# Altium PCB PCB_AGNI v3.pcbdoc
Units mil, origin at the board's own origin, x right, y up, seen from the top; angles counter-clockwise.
Board outline 4895 x 4505 mil, 4 copper layers (Top Layer, GND, GND (Plane2), Bottom Layer); 85 components, 70 nets, 368 pads, 99 vias.
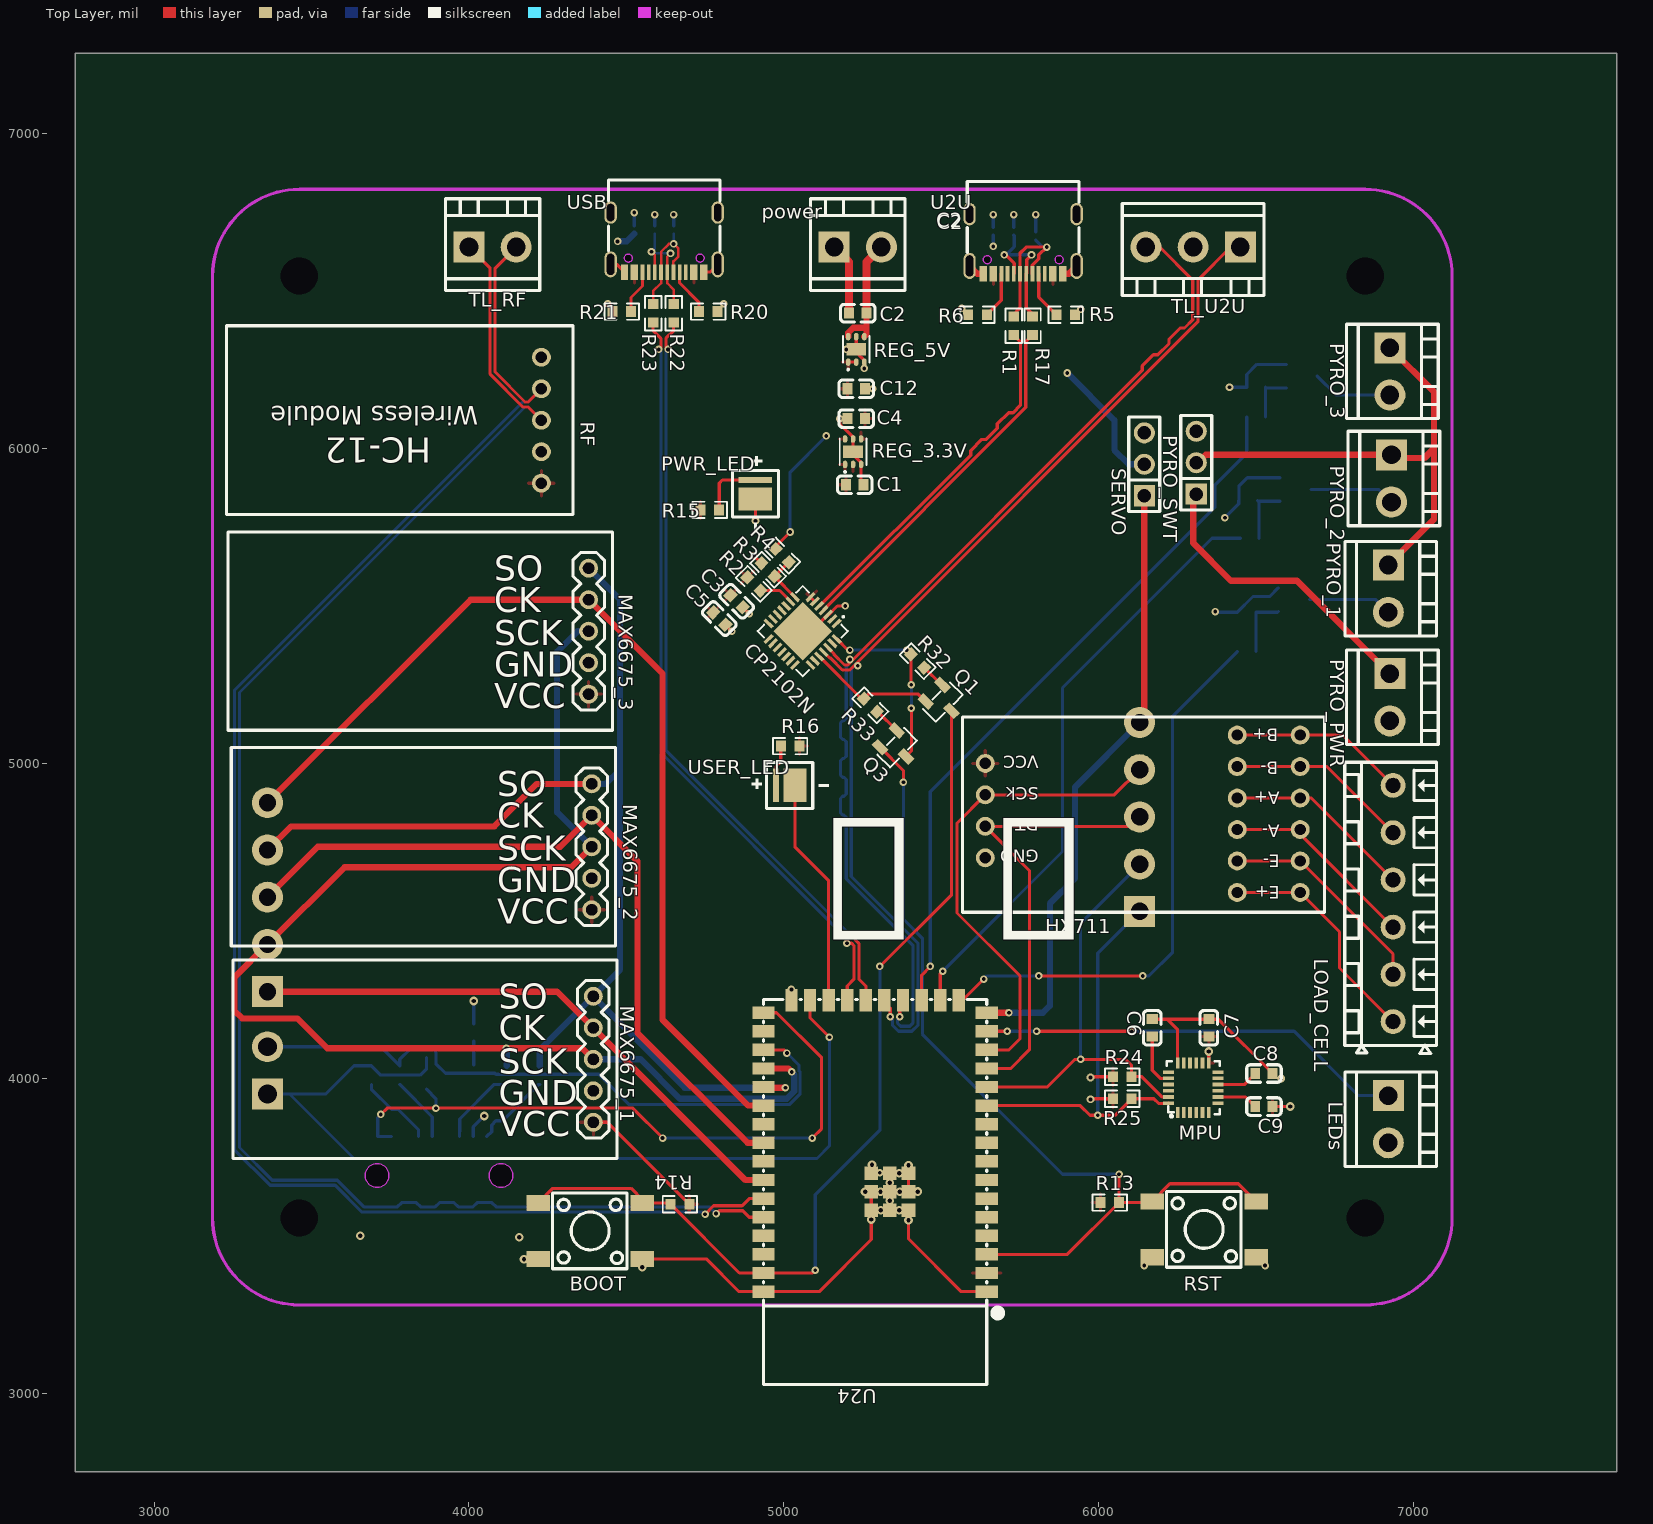
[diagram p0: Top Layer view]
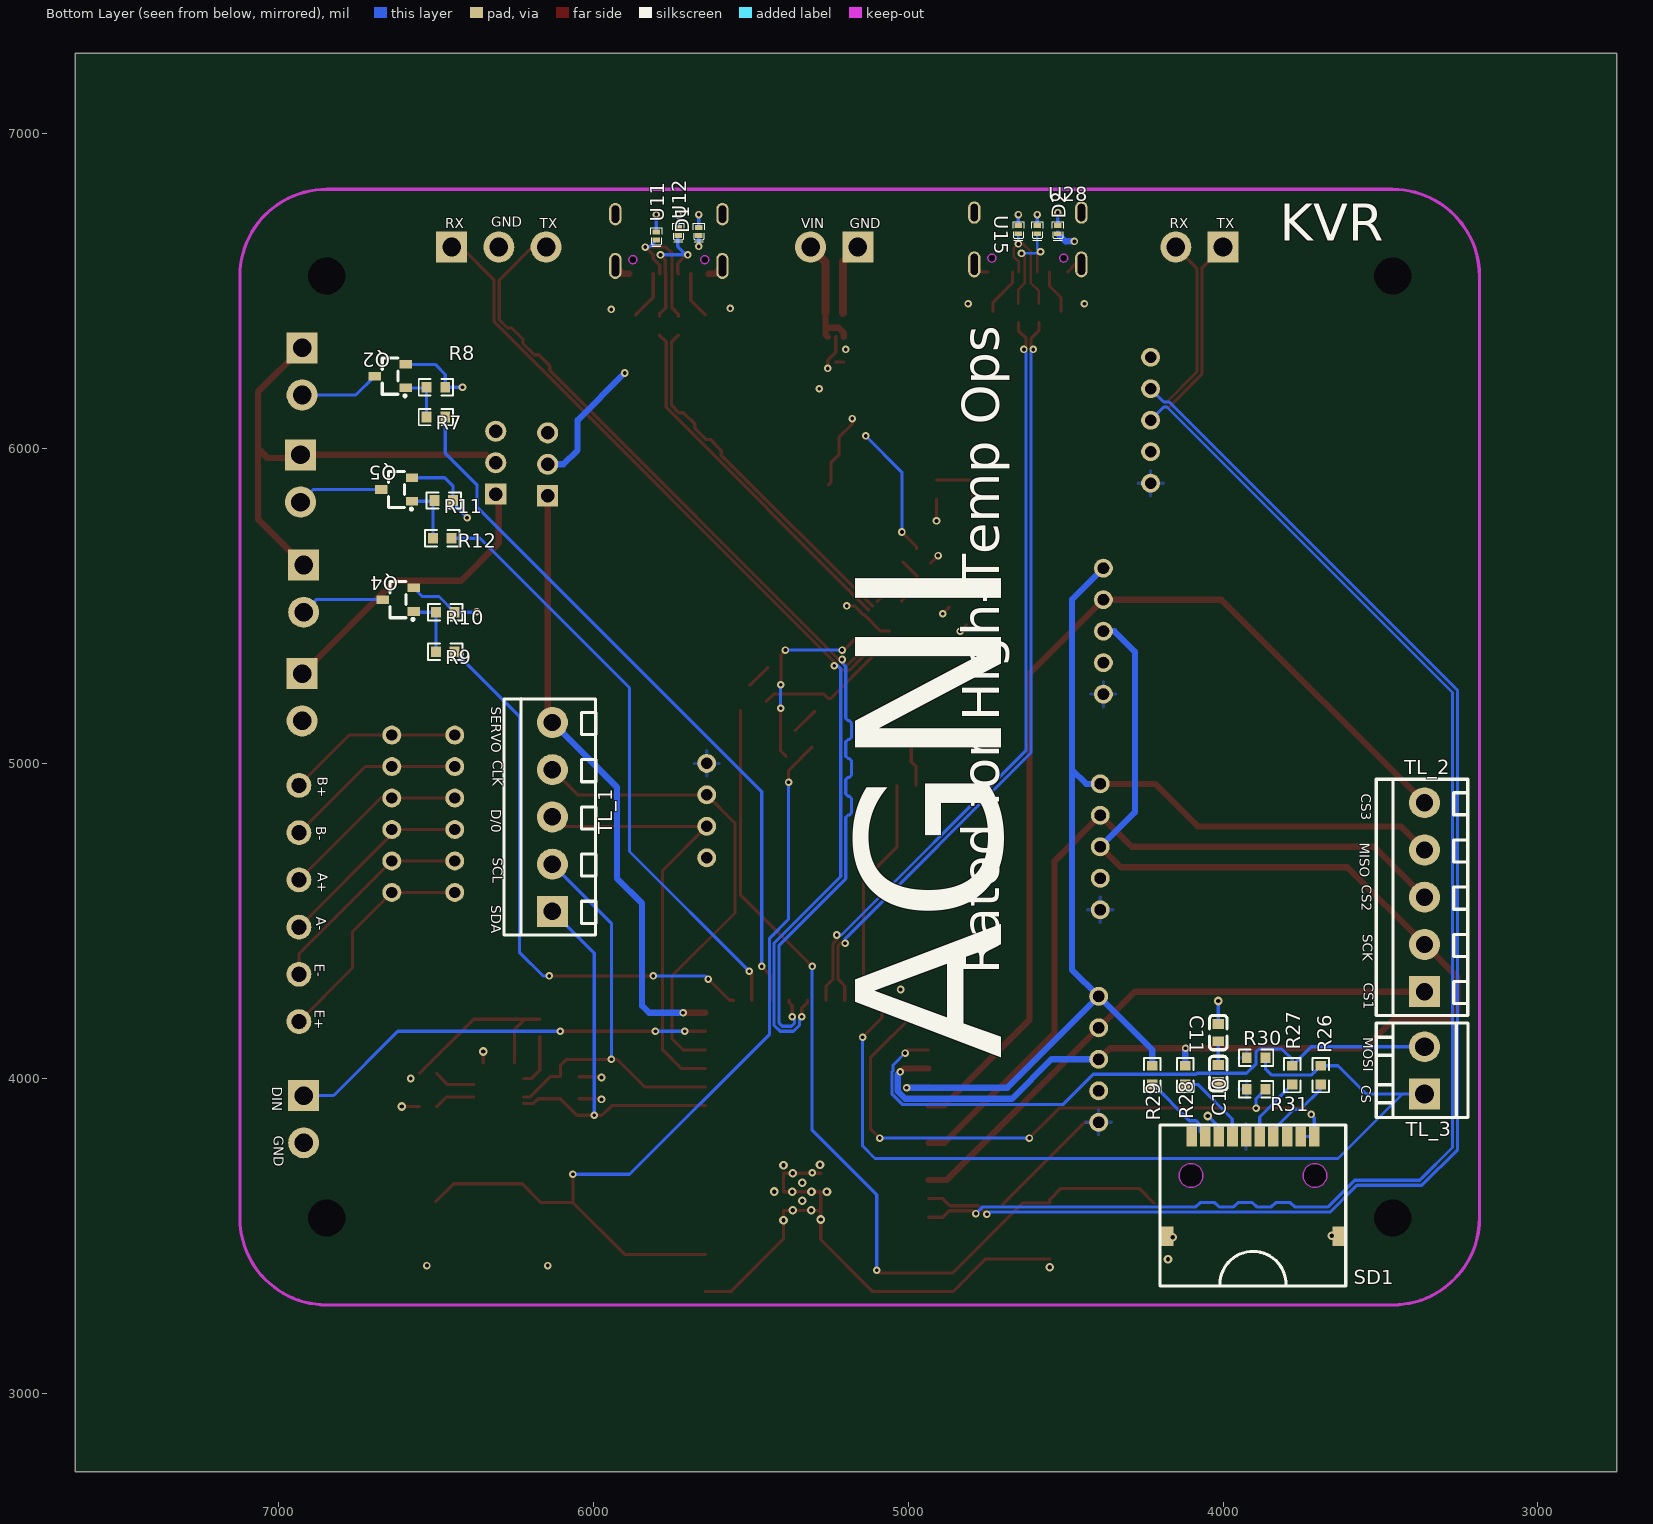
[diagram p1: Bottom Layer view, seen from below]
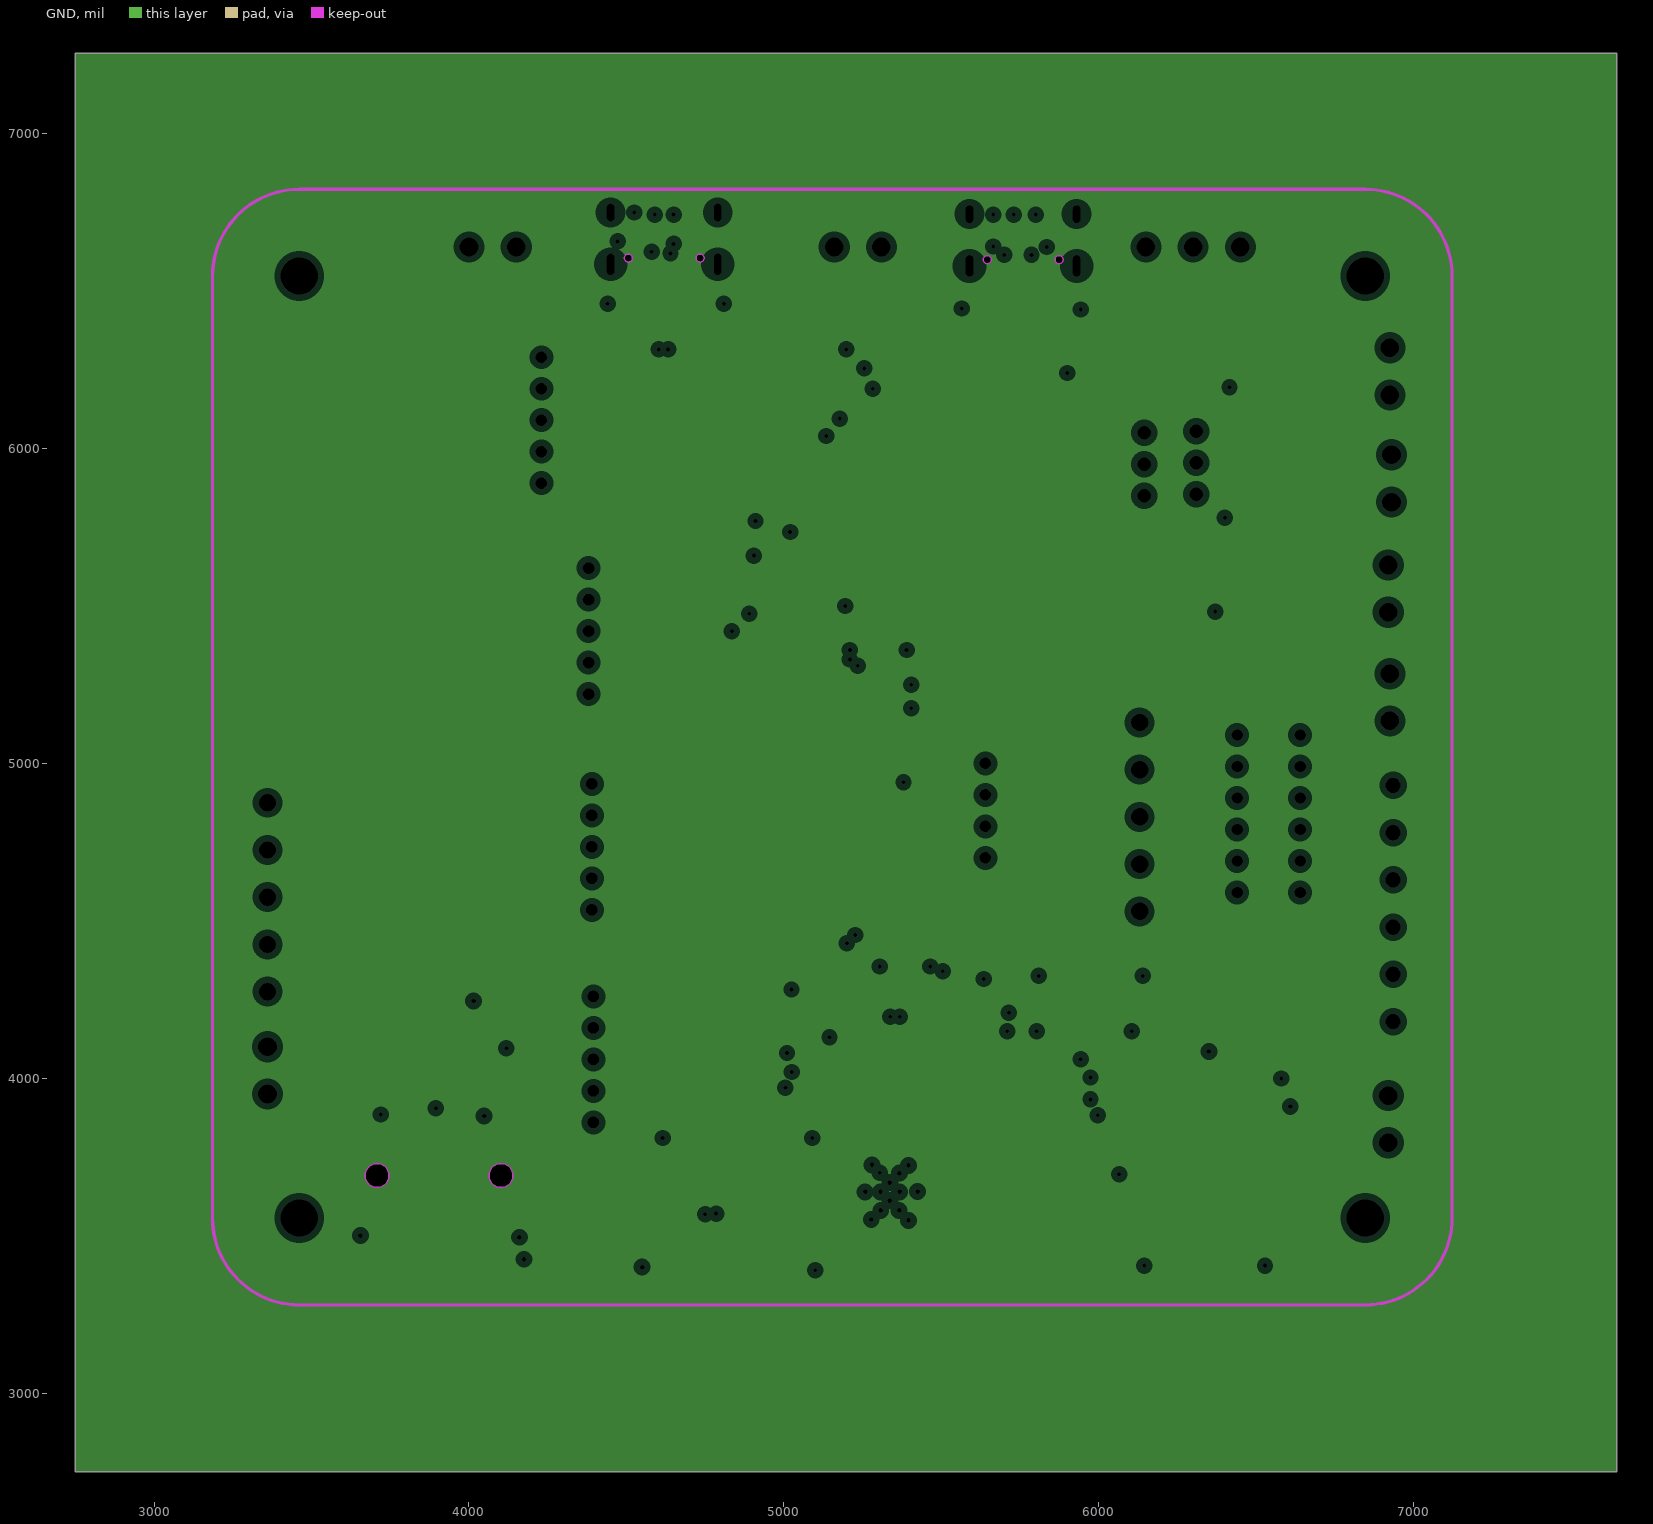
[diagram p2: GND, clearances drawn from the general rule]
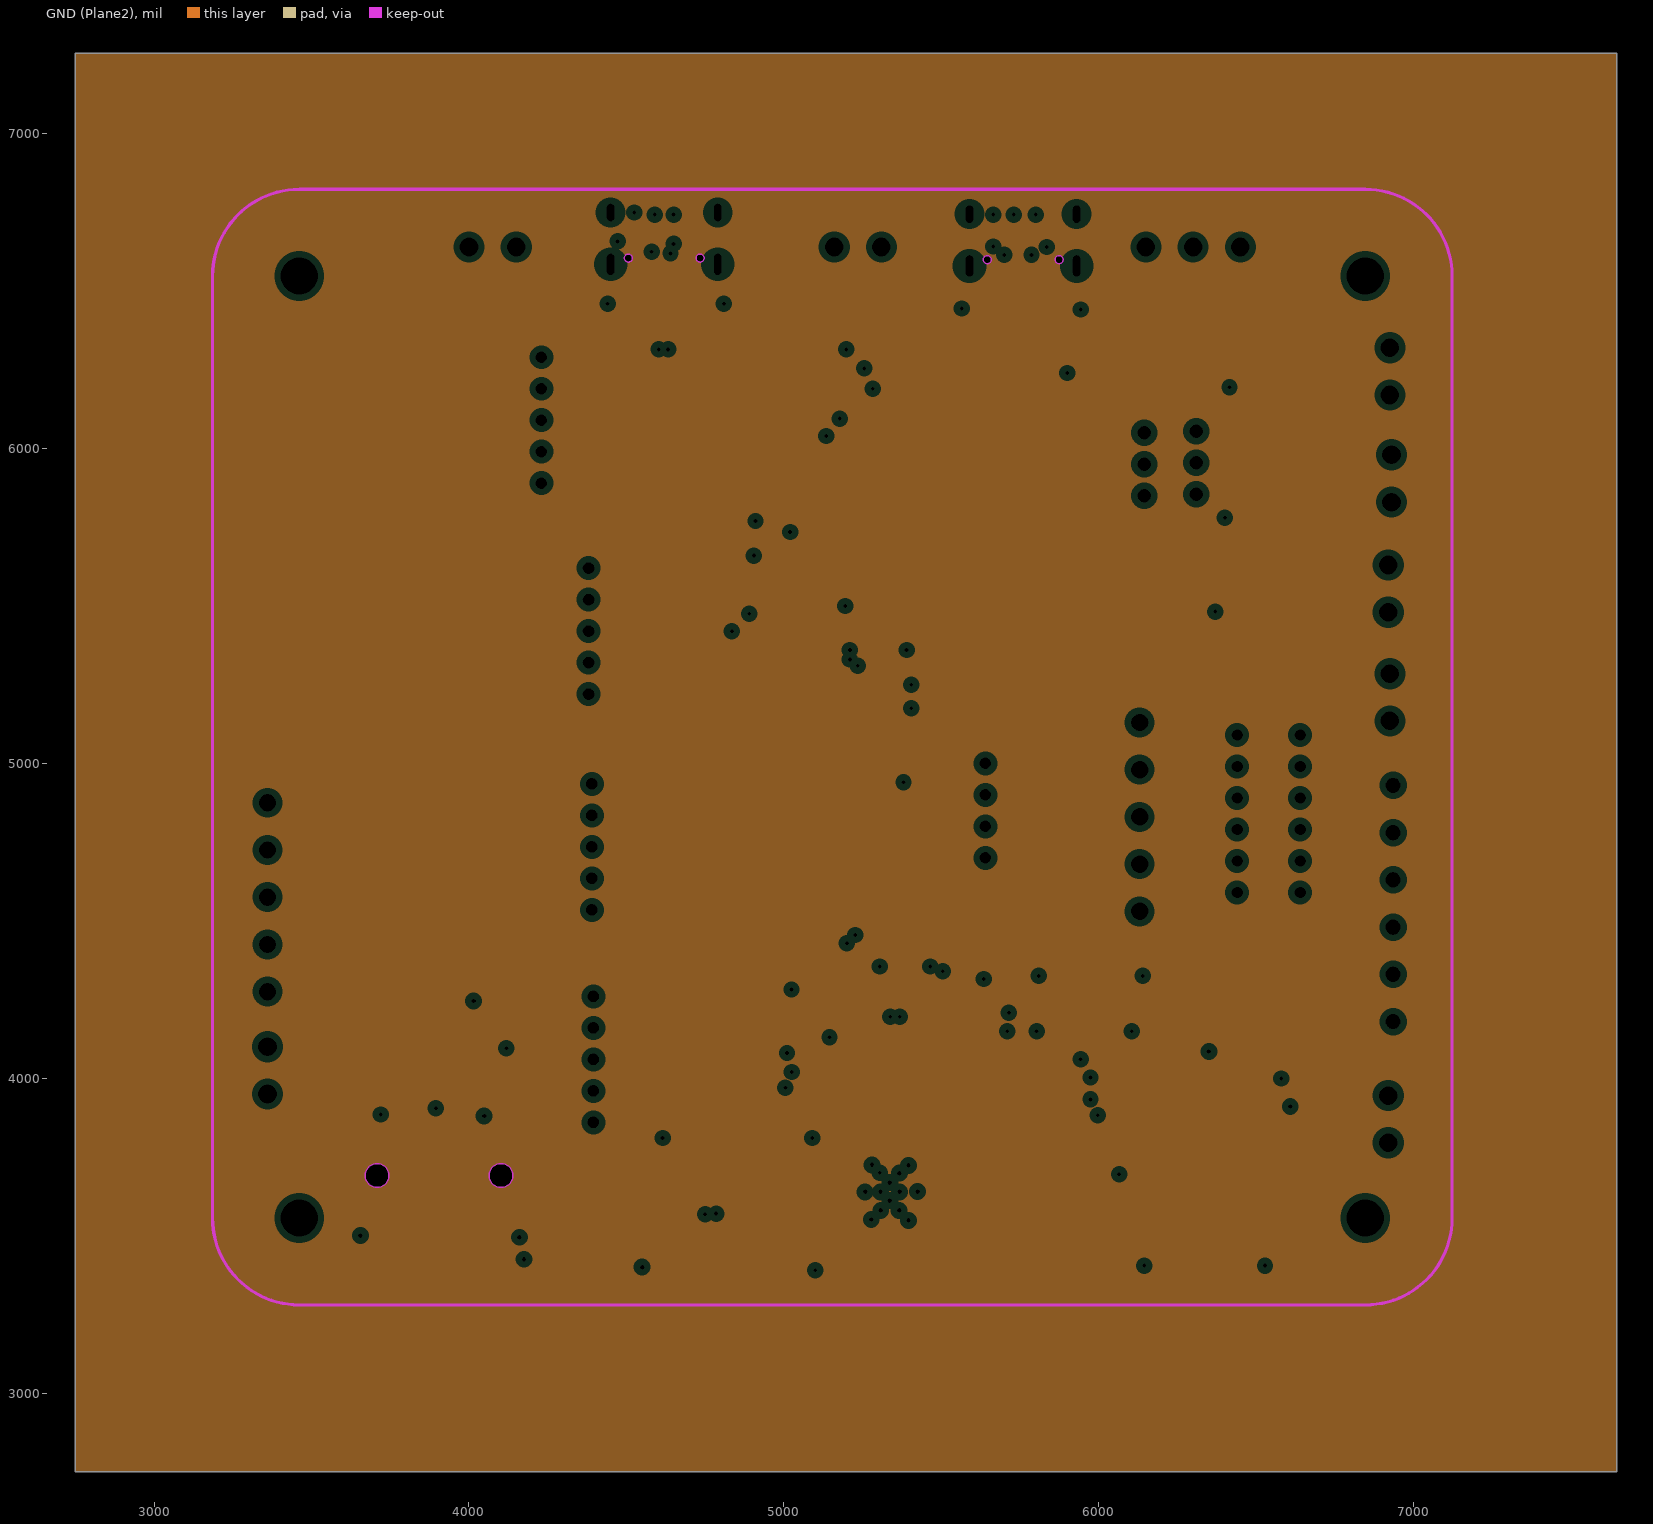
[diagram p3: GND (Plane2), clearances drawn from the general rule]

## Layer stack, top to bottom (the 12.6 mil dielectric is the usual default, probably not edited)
Top Layer: signal copper (thickness not stored)
Dielectric: dielectric 12.6, FR-4, Dk 4.8
GND: plane copper (thickness not stored)
Dielectric: dielectric 12.6, FR-4, Dk 4.8
GND (Plane2): plane copper (thickness not stored)
Dielectric: dielectric 12.6, FR-4, Dk 4.8
Bottom Layer: signal copper (thickness not stored)

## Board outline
7645,2750 2750,2750 2750,7255 7645,7255

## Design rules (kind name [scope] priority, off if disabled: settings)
BoardOutlineClearance copperThickness1oz [All] p0: genericclearance=10 ignorepadtopadclearanceinfootprint=FALSE except(0: Arc-SplitContinuation Track-SplitContinuation SMDPad-SplitContinuation THPad-SplitContinuation Via-SplitContinuation Fill-SplitContinuation Poly-SplitContinuation Region-SplitContinuation Text-SplitContinuation; 6: SMDPad-CutoutEdge THPad-CutoutEdge Via-CutoutEdge Fill-CutoutEdge Region-CutoutEdge; 11.8: Track-OutlineEdge SMDPad-OutlineEdge THPad-OutlineEdge Via-OutlineEdge Fill-OutlineEdge Region-OutlineEdge Poly-OutlineEdge Text-OutlineEdge Track-CutoutEdge)
BoardOutlineClearance copperThickness2oz [All] p0: genericclearance=10 ignorepadtopadclearanceinfootprint=FALSE except(0: Arc-SplitContinuation Track-SplitContinuation SMDPad-SplitContinuation THPad-SplitContinuation Via-SplitContinuation Fill-SplitContinuation Poly-SplitContinuation Region-SplitContinuation Text-SplitContinuation; 6: SMDPad-CutoutEdge THPad-CutoutEdge Via-CutoutEdge Fill-CutoutEdge Region-CutoutEdge; 11.8: Track-OutlineEdge SMDPad-OutlineEdge THPad-OutlineEdge Via-OutlineEdge Fill-OutlineEdge Region-OutlineEdge Poly-OutlineEdge Text-OutlineEdge Track-CutoutEdge)
BoardOutlineClearance copperThicknessInner0.5oz [All] p0: genericclearance=10 ignorepadtopadclearanceinfootprint=FALSE except(0: Arc-SplitContinuation Track-SplitContinuation SMDPad-SplitContinuation THPad-SplitContinuation Via-SplitContinuation Fill-SplitContinuation Poly-SplitContinuation Region-SplitContinuation Text-SplitContinuation; 6: SMDPad-CutoutEdge THPad-CutoutEdge Via-CutoutEdge Fill-CutoutEdge Region-CutoutEdge; 11.8: Track-OutlineEdge SMDPad-OutlineEdge THPad-OutlineEdge Via-OutlineEdge Fill-OutlineEdge Region-OutlineEdge Poly-OutlineEdge Text-OutlineEdge Track-CutoutEdge)
Clearance copperThickness1oz [(InNet('USB_D+') OR InNet('USB_D-') OR InNet('D+') OR InNet('D-') OR InNet('VIN') OR InNet('GND') OR InNet('+5V') OR InNet('MOSI') OR InNet('CS') OR InNet('PYRO-3') OR InNet('PYRO-1') OR InNet('PYRO-2') OR InNet('CD') OR InNet('3.3') OR InNet('SCK') OR InNet('MISO') OR InNet('CS3') OR InNet('CS2') OR InNet('CS1') OR InNet('SERVO_HIGH') OR InNet('CLK') OR InNet('D/O') OR InNet('SCL') OR InNet('SDA') OR InNet('PYRO_5V') OR InNet('PYRO_ARM') OR InNet('UART_D+') OR InNet('UART_D-') OR InNet('RTS') OR InNet('U2U_RX') OR InNet('U2U_TX') OR InNet('DTR') OR InNet('IO0') OR InNet('EN') OR InNet('RF_TX') OR InNet('RF_RX') OR InNet('LED_USER') OR InNet('DIN_LED') OR InNet('$1N118') OR InNet('$1N2149') OR InNet('$1N121') OR InNet('$1N129') OR InNet('1D-') OR InNet('$1N23') OR InNet('$1N18') OR InNet('$1N68') OR InNet('$1N69') OR InNet('$1N96') OR InNet('$1N98') OR InNet('$1N99') OR InNet('1D+') OR InNet('$1N9') OR InNet('$1N8') OR InNet('$1N134') OR InNet('$1N147') OR InNet('$1N149') OR InNet('$1N41') OR InNet('$1N48') OR InNet('$1N36') OR InNet('$1N102') OR InNet('$1N103') OR InNet('$1N106') OR InNet('$1N105') OR InNet('$1N104') OR InNet('$1N190') OR InNet('$1N40') OR InNet('$1N49') OR InNet('$1N123') OR InNet('$1N125') OR InNet('$1N131'))] p1: gap=7 ignorepadtopadclearanceinfootprint=FALSE except(4: Track-Track; 6: Track-SMDPad SMDPad-SMDPad Track-THPad SMDPad-THPad THPad-THPad Track-Via SMDPad-Via THPad-Via Via-Via Track-Fill SMDPad-Fill THPad-Fill Via-Fill Fill-Fill SMDPad-Region THPad-Region Via-Region Fill-Region Region-Region Track-Poly SMDPad-Poly THPad-Poly Via-Poly Fill-Poly Poly-Poly Track-Text SMDPad-Text THPad-Text Via-Text Fill-Text Region-Text Poly-Text Text-Text; 6.9: Track-Hole SMDPad-Hole THPad-Hole Via-Hole Fill-Hole Region-Hole Poly-Hole Text-Hole Sheet-Hole; 11.8: Track-Region Region-Poly Track-Sheet SMDPad-Sheet THPad-Sheet Via-Sheet Fill-Sheet Region-Sheet Poly-Sheet Text-Sheet)
Clearance copperThickness2oz [All] p1: gap=7 ignorepadtopadclearanceinfootprint=FALSE except(6: Track-SMDPad SMDPad-SMDPad Track-THPad SMDPad-THPad THPad-THPad Track-Via SMDPad-Via THPad-Via Via-Via Track-Fill SMDPad-Fill THPad-Fill Via-Fill Fill-Fill SMDPad-Region THPad-Region Via-Region Fill-Region Region-Region Track-Poly SMDPad-Poly THPad-Poly Via-Poly Fill-Poly Poly-Poly Track-Text SMDPad-Text THPad-Text Via-Text Fill-Text Region-Text Poly-Text Text-Text; 6.9: Track-Hole SMDPad-Hole THPad-Hole Via-Hole Fill-Hole Region-Hole Poly-Hole Text-Hole Sheet-Hole; 8: Track-Track; 11.8: Track-Region Region-Poly Track-Sheet SMDPad-Sheet THPad-Sheet Via-Sheet Fill-Sheet Region-Sheet Poly-Sheet Text-Sheet)
Clearance copperThicknessInner0.5oz [All] p1: gap=7 ignorepadtopadclearanceinfootprint=FALSE except(3.5: Track-Track; 6: Track-SMDPad SMDPad-SMDPad Track-THPad SMDPad-THPad THPad-THPad Track-Via SMDPad-Via THPad-Via Via-Via Track-Fill SMDPad-Fill THPad-Fill Via-Fill Fill-Fill SMDPad-Region THPad-Region Via-Region Fill-Region Region-Region Track-Poly SMDPad-Poly THPad-Poly Via-Poly Fill-Poly Poly-Poly Track-Text SMDPad-Text THPad-Text Via-Text Fill-Text Region-Text Poly-Text Text-Text; 6.9: Track-Hole SMDPad-Hole THPad-Hole Via-Hole Fill-Hole Region-Hole Poly-Hole Text-Hole Sheet-Hole; 11.8: Track-Region Region-Poly Track-Sheet SMDPad-Sheet THPad-Sheet Via-Sheet Fill-Sheet Region-Sheet Poly-Sheet Text-Sheet)
DiffPairsRouting differentialPair [All] p1: maxuncoupledlength=10 minlimit=5.9843 maxlimit=5.9843 mostfreqgap=5.9843 toplayer_minwidth=5 toplayer_prefwidth=10 toplayer_maxwidth=100 bottomlayer_minwidth=5 bottomlayer_prefwidth=10 bottomlayer_maxwidth=100
PasteMaskExpansion pasteMaskExpansion [All] p1: expansion=0
PlaneConnect innerPlane [All] p1: planeconnectstyle=Relief reliefexpansion=20 reliefentries=4 reliefconductorwidth=10 reliefairgap=10
PolygonConnect copperRegion [All] p1: connectstyle=Relief reliefentries=4 reliefconductorwidth=10 polygonreliefangle="90 Angle" airgapwidth=10
RoutingVias viaSize [All] p1: viastyle="Through Hole" holewidth=12.0078 minholewidth=7.874 maxholewidth=248.0314 width=24.0158 minwidth=11.811 maxwidth=393.7008
SolderMaskExpansion solderMaskExpansion [All] p1: useseparateexpansions=TRUE expansion=2.0079 expansionbottom=2.0079
Width copperThickness1oz [All] p1: maxlimit=100 minlimit=4 preferedwidth=10
Width copperThickness0.5oz [All] p1: maxlimit=100 minlimit=4 preferedwidth=10
Width copperThickness2oz [All] p1: maxlimit=100 minlimit=8 preferedwidth=10

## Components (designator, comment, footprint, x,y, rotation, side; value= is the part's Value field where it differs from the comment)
BOOT "PTS645SH50SMTR92LFS" KEY-SMD_4P-L6.0-W6.0-P4.50-LS9.0 4385,3515 r0 top locked
C1 "2.2uF" C0603 5225,5885 r180 top locked
C2 "1uF" C0603 5235,6430 r0 top locked
C3 "10uF" C0603 4850,5515 r135 top locked
C4 "1uF" C0603 5230,6095 r0 top locked
C5 "10uF" C0603 4795,5460 r135 top locked
C6 "2.2nF" C0603 6170,4160 r270 top locked
C7 "0.1uF" C0603 6350,4160 r90 top locked
C8 "0.1uF" C0603 6525,4015 r180 top locked
C9 "10nF" C0603 6525,3910 r0 top locked
C10 "0.1uF" C0603 4015,4015 r270 bottom locked
C11 "10uF" C0603 4015,4145 r270 bottom locked
C12 "2.2uF" C0603 5230,6190 r180 top locked
CP2102N "CP2102N-A02-GQFN28R" QFN-28_L5.0-W5.0-P0.50-TL-EP3.3 5060,5420 r225 top locked
D1 "ESD351DPYR" X1SON-2_L1.0-W0.6-P0.65-RD-1 5665,6690 r90 bottom locked
D2 "ESD351DPYR" X1SON-2_L1.0-W0.6-P0.65-RD-1 4525,6695 r90 bottom locked
HX711 "HX711 LOAD CELL AMPLIFIER COMBINE" "HX711 LOAD CELL AMPLIFIER HX711 BREAKOUT" 6140,4840 r180 top locked
LEDs "DB125-3.81-2P-RD" CONN-TH_DB125-3.81-2P-RD 6920,3870 r270 top locked
LOAD_CELL "DB125-3.81-6P-GN-S" CONN-TH_DB125-3.81-6P-GN-S 6935,4555 r90 top locked
MAX6675_1 "MAX6675" MAX6675 4395,4060 r0 top locked
MAX6675_2 "MAX6675" MAX6675 4390,4735 r0 top locked
MAX6675_3 "MAX6675" MAX6675 4380,5420 r0 top locked
MPU "MPU6050_C9900042518" QFN-24_L4.0-W4.0-P0.50-BL 6300.01,3970.04 r0 top locked
power "DB125-3.81-2P-RD" CONN-TH_DB125-3.81-2P-RD 5235,6640 r0 top locked
PWR_LED "720-LCGH9RNMXNX1" LED-SMD_SD65-120-LED 4910,5870 r90 top locked
PYRO_1 "DB125-3.81-2P-RD" CONN-TH_DB125-3.81-2P-RD 6920,5555 r270 top locked
PYRO_2 "DB125-3.81-2P-RD" CONN-TH_DB125-3.81-2P-RD 6930,5905 r270 top locked
PYRO_3 "DB125-3.81-2P-RD" CONN-TH_DB125-3.81-2P-RD 6925,6245 r270 top locked
PYRO_PWR "DB125-3.81-2P-RD" CONN-TH_DB125-3.81-2P-RD 6925,5210 r270 top locked
PYRO_SWT "HDR-M_2.54_1x3P" HDR-TH_3P-P2.54-V-M 6310,5955 r90 top locked
Q1 "SS8050G-Y1" SOT-23-3_L2.9-W1.3-P1.90-LS2.4-BR 5505,5195 r135 top locked
Q2 "A03400" SOT-23-3_L2.9-W1.3-P1.90-LS2.6-BR 6645,6230 r180 bottom locked
Q3 "SS8050G-Y1" SOT-23-3_L2.9-W1.3-P1.90-LS2.4-BR 5360,5050 r135 top locked
Q4 "A03400" SOT-23-3_L2.9-W1.3-P1.90-LS2.6-BR 6620,5520 r180 bottom locked
Q5 "A03400" SOT-23-3_L2.9-W1.3-P1.90-LS2.6-BR 6625,5870 r180 bottom locked
R1 "22" R0603 5730,6390 r90 top locked
R2 "1k" R0603 4905,5570 r135 top locked
R3 "47K" R0603 4950,5615 r135 top locked
R4 "24K" R0603 4995,5660 r315 top locked
R5 "5.1K" R0603 5895,6425 r180 top locked
R6 "5.1k" R0603 5615,6425 r0 top locked
R7 "220" R0603 6500,6100 r0 bottom locked
R8 "10K" R0603 6500,6195 r0 bottom locked
R9 "220" R0603 6470,5355 r0 bottom locked
R10 "10K" R0603 6470,5480 r0 bottom locked
R11 "10K" R0603 6475,5835 r0 bottom locked
R12 "220" R0603 6480,5715 r0 bottom locked
R13 "10K" R0603 6035,3605 r180 top locked
R14 "10K" R0603 4670,3600 r0 top locked
R15 "220" R0603 4765,5805 r180 top locked
R16 "220" R0603 5020,5055 r0 top locked
R17 "22" R0603 5790,6390 r90 top locked
R20 "5.1K" R0603 4760,6435 r180 top locked
R21 "5.1k" R0603 4485,6435 r0 top locked
R22 "22" R0603 4650,6430 r90 top locked
R23 "22" R0603 4585,6430 r90 top locked
R24 "4.7K" R0603 6075,4005 r0 top locked
R25 "4.7K" R0603 6075,3935 r180 top locked
R26 "33" R0603 3690,4010 r90 bottom locked
R27 "33" R0603 3780,4010 r90 bottom locked
R28 "33" R0603 4120,4010 r90 bottom locked
R29 "33" R0603 4225,4010 r90 bottom locked
R30 "4.7" R0603 3895,4065 r180 bottom locked
R31 "10k" R0603 3895,3965 r180 bottom locked
R32 "10K" R0603 5425,5325 r135 top locked
R33 "10K" R0603 5275,5185 r135 top locked
REG_3.3V "TLV76733DRVT" WSON-6_L2.0-W2.0-P0.65-TL-EP 5220,5990 r90 top locked
REG_5V "TLV76750DRVT" WSON-6_L2.0-W2.0-P0.65-TL-EP 5230,6315 r90 top locked
RF "HC-12 SI44663" "HC-12 SI4463 WIRELESS MODULE" 4330,5790 r180 top locked
RST "PTS645SH50SMTR92LFS" KEY-SMD_4P-L6.0-W6.0-P4.50-LS9.0 6335,3520 r0 top locked
SD1 "SUNROM 6174" "SUNROM 6174" 3905,3815 r0 bottom locked
SERVO "HDR-M_2.54_1x3P" HDR-TH_3P-P2.54-V-M 6145,5950 r90 top locked
TL_1 "DB125-3.81-5P-GN-S" CONN-TH_DB125-3.81-5P-GN-S 6130,4830 r90 bottom locked
TL_2 "DB125-3.81-5P-GN-S" CONN-TH_DB125-3.81-5P-GN-S 3360,4575 r90 bottom locked
TL_3 "DB125-3.81-2P-RD" CONN-TH_DB125-3.81-2P-RD 3360,4025 r90 bottom locked
TL_RF "DB125-3.81-2P-RD" CONN-TH_DB125-3.81-2P-RD 4075,6640 r0 top locked
TL_U2U "DB125-3.81-3P-BK" CONN-TH_DB125-3.81-3P-BK 6300,6640 r180 top locked
U2U "GT-USB-7010ASV" USB-C-SMD_G-SWITCH_GT-USB-7010ASV 5760,6650 r180 top locked
U11 "ESD321DPYR" X1SON-2_L1.0-W0.6-P0.65-RD 5800,6675 r90 bottom locked
U12 "ESD321DPYR" X1SON-2_L1.0-W0.6-P0.65-RD 5730,6690 r90 bottom locked
U15 "ESD321DPYR" X1SON-2_L1.0-W0.6-P0.65-RD 4650,6695 r90 bottom locked
U24 "ESP32-S2-WROOM(4M)" WIFI-SMD_ESP32-S2-WROVER-I 5290,3785 r180 top locked
U28 "ESD321DPYR" X1SON-2_L1.0-W0.6-P0.65-RD 4590,6695 r90 bottom locked
USB "GT-USB-7010ASV" USB-C-SMD_G-SWITCH_GT-USB-7010ASV 4620,6655 r180 top locked
USER_LED "720-LCGH9RNMXNX1" LED-SMD_SD65-120-LED 5005,4930 r180 top locked

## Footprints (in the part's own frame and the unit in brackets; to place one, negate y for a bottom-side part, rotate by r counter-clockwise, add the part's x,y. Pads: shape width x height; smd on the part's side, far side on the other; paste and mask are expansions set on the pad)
C0603 [mm]
  rect 0.8x0.9 smd: 1(-0.7,0) 2(0.7,0)
  silkscreen extent -1.39,-0.71 1.39,0.71
CONN-TH_DB125-3.81-2P-RD [mm]
  rect 2.5x2.5 hole 1.5: 1(-1.905,0)
  round 2.5 hole 1.5: 2(1.905,0)
  silkscreen extent -3.81,-3.5 3.81,3.9
CONN-TH_DB125-3.81-3P-BK [mm]
  rect 2.5x2.5 hole 1.5: 1(-3.81,0)
  round 2.5 hole 1.5: 2(0,0) 3(3.81,0)
  silkscreen extent -5.72,-3.5 5.72,3.9
CONN-TH_DB125-3.81-5P-GN-S [mm]
  rect 2.5x2.5 hole 1.4: 1(-7.62,0)
  round 2.5 hole 1.4: 2(-3.81,0) 3(0,0) 4(3.81,0) 5(7.62,0)
  silkscreen extent -9.53,-3.5 9.53,3.9
CONN-TH_DB125-3.81-6P-GN-S [mm]
  round 2 hole 1.2 slot 1.205 at 0 deg: 1(-9.525,0) 2(-5.715,0) 3(-1.905,0) 4(1.905,0) 5(5.715,0) 6(9.525,0)
  silkscreen extent -12.1,-3.5 11.4,3.9
"HC-12 SI4463 WIRELESS MODULE" [mil]
  round 60 hole 36: 1(100,-100) 2(100,-200) 3(100,-300) 4(100,-400) 5(100,-500)
  silkscreen extent 0,-600 1100,0
HDR-TH_3P-P2.54-V-M [mm]
  rect 1.7x1.7 hole 1.1: 1(-2.54,0)
  round 1.7 hole 1.1: 2(0,0) 3(2.54,0)
  silkscreen extent -3.81,-1.25 3.81,1.25
"HX711 LOAD CELL AMPLIFIER HX711 BREAKOUT" [mil]
  round 60 hole 36 copper offset -0.01,0.01: 1(-499.99,249.99) 1(-299.99,249.99) 2(-499.99,149.99) 2(-299.99,149.99) 3(-499.99,49.99) 3(-299.99,49.99) 4(-499.99,-50.01) 4(-299.99,-50.01) 5(-499.99,-150.01) 5(-299.99,-150.01) 6(-499.99,-250.01) 6(-299.99,-250.01) 8(500.01,39.99) 9(500.01,-60.01) 10(500.01,-160.01)
  round 60 hole 36 copper offset -0.01,0: 7(500.01,140)
  silkscreen extent -577,-308 573,313
KEY-SMD_4P-L6.0-W6.0-P4.50-LS9.0 [mm]
  rect 1.9x1.3 smd: 1(-4.2,2.25) 2(4.2,2.25) 3(-4.2,-2.25) 4(4.2,-2.25)
  silkscreen extent -3.05,-3.05 2.98,3.05
LED-SMD_SD65-120-LED [mm]
  rect 1.85x2.7 smd: 1(-0.763,0)
  rect 0.5x2.7 smd: 2(0.763,0)
  silkscreen extent -3.5,-1.85 2.7,1.85
MAX6675 [mil]
  round 60 hole 36 slot 36.2 at 0 deg: 1(0,200) 2(0,100) 3(0,0) 4(0,-100) 5(0,-200)
  silkscreen extent -1145,-315 75,315
QFN-24_L4.0-W4.0-P0.50-BL [mm]
  rect 0.3x0.9 smd: 1(-1.25,-2) 2(-0.75,-2) 3(-0.25,-2) 4(0.25,-2) 5(0.75,-2) 6(1.25,-2) 13(1.25,2) 14(0.75,2) 15(0.25,2) 16(-0.25,2) 17(-0.75,2) 18(-1.25,2)
  rect 0.9x0.3 smd: 7(2,-1.25) 8(2,-0.75) 9(2,-0.25) 10(2,0.25) 11(2,0.75) 12(2,1.25) 19(-2,1.25) 20(-2,0.75) 21(-2,0.25) 22(-2,-0.25) 23(-2,-0.75) 24(-2,-1.25)
  silkscreen extent -2.14,-2.4 2.16,2.15
QFN-28_L5.0-W5.0-P0.50-TL-EP3.3 [mm]
  rect 0.905x0.28 smd: 1(-2.377,1.5) 2(-2.377,1) 3(-2.377,0.5) 4(-2.378,0) 5(-2.377,-0.5) 6(-2.377,-1) 7(-2.377,-1.5) 15(2.377,-1.5) 16(2.377,-1) 17(2.377,-0.5) 18(2.378,0) 19(2.377,0.5) 20(2.377,1) 21(2.377,1.5)
  rect 0.28x0.905 smd: 8(-1.5,-2.377) 9(-1,-2.377) 10(-0.5,-2.377) 11(0,-2.378) 12(0.5,-2.377) 13(1,-2.377) 14(1.5,-2.377) 22(1.5,2.377) 23(1,2.377) 24(0.5,2.377) 25(0,2.378) 26(-0.5,2.377) 27(-1,2.377) 28(-1.5,2.377)
  rect 3.35x3.35 smd: 29(0,0)
  silkscreen extent -3.2,-2.58 2.58,2.58
R0603 [mil]
  rect 31.75x34.02 smd: 1(-29.66,0) 2(29.66,0)
  silkscreen extent -55,-26 55,26
SOT-23-3_L2.9-W1.3-P1.90-LS2.4-BR [mm]
  rect 1.25x0.7 smd: 1(1,-0.95) 2(1,0.95) 3(-1,0)
  silkscreen extent -0.73,-1.53 0.73,1.53
SOT-23-3_L2.9-W1.3-P1.90-LS2.6-BR [mm]
  rect 1x0.7 smd: 1(1.25,-0.95) 2(1.25,0.95) 3(-1.25,0)
  silkscreen extent -0.65,-1.69 1.29,1.46
"SUNROM 6174" [mm]
  rect 0.85x1.6 smd: 1(-2.75,0) 2(-1.65,0) 3(-0.55,0) 4(0.55,0) 5(1.65,0) 6(2.75,0) 7(3.85,0) 8(4.95,0) 9(-4.95,0) 10(-3.85,0)
  rect 1.15x1.6 smd: 11(-6.99,8.05) 12(6.99,8.05)
  Board Outline Layer lines w0.005: -5.003,2.198 cw(c-5.001,3.15) -5,2.198 -5.003,2.198 ; 4.997,2.198 cw(c4.999,3.15) 5,2.198 4.997,2.198
  Board Outline Layer region: -5,2.198 -4.524,2.326 -4.176,2.675 -4.049,3.151 -4.177,3.626 -4.525,3.975 -5.001,4.102 -5.477,3.975 -5.825,3.626 -5.953,3.151 -5.826,2.675 -5.478,2.326 -5.003,2.198 -5.003,2.198
  Board Outline Layer region: 5,2.198 5.476,2.326 5.824,2.675 5.951,3.151 5.823,3.626 5.475,3.975 4.999,4.102 4.523,3.975 4.174,3.626 4.047,3.151 4.174,2.675 4.522,2.326 4.997,2.198 4.997,2.198
  Multi-Layer board cut-out: -5,2.198 -4.524,2.326 -4.176,2.675 -4.049,3.151 -4.177,3.626 -4.525,3.975 -5.001,4.102 -5.477,3.975 -5.825,3.626 -5.953,3.151 -5.826,2.675 -5.478,2.326 -5.003,2.198 -5.003,2.198
  Multi-Layer board cut-out: 5,2.198 5.476,2.326 5.824,2.675 5.951,3.151 5.823,3.626 5.475,3.975 4.999,4.102 4.523,3.975 4.174,3.626 4.047,3.151 4.174,2.675 4.522,2.326 4.997,2.198 4.997,2.198
  silkscreen extent -7.49,-0.93 7.51,12.06
USB-C-SMD_G-SWITCH_GT-USB-7010ASV [mm]
  oval 1x2.1 hole 0.6 slot 1.7 at 90 deg: 1(-4.32,1.78) 2(4.32,1.78)
  oval 1x1.8 hole 0.6 slot 1.4 at 90 deg: 3(4.32,-2.4) 4(-4.32,-2.4)
  rect 0.6x1.24 smd: A1B12(-3.2,2.4) A4B9(-2.4,2.4) B1A12(3.2,2.4) B4A9(2.4,2.4)
  rect 0.3x1.24 smd: A5(-1.25,2.4) A6(-0.25,2.4) A7(0.25,2.4) A8(1.25,2.4) B5(1.75,2.4) B6(0.75,2.4) B7(-0.75,2.4) B8(-1.75,2.4)
  Board Outline Layer circle w0.005: c2.89,1.27 r0.325
  Board Outline Layer circle w0.005: c-2.9,1.27 r0.325
  Board Outline Layer region: 2.565,1.27 2.597,1.411 2.687,1.524 2.818,1.587 2.962,1.587 3.093,1.524 3.183,1.411 3.215,1.27 3.215,1.27 3.183,1.129 3.093,1.016 2.962,0.953 2.818,0.953 2.687,1.016 2.597,1.129 2.565,1.27
  Board Outline Layer region: -3.225,1.27 -3.193,1.411 -3.103,1.524 -2.972,1.587 -2.828,1.587 -2.697,1.524 -2.607,1.411 -2.575,1.27 -2.575,1.27 -2.607,1.129 -2.697,1.016 -2.828,0.953 -2.972,0.953 -3.103,1.016 -3.193,1.129 -3.225,1.27
  Multi-Layer board cut-out: 2.565,1.27 2.597,1.411 2.687,1.524 2.818,1.587 2.962,1.587 3.093,1.524 3.183,1.411 3.215,1.27 3.215,1.27 3.183,1.129 3.093,1.016 2.962,0.953 2.818,0.953 2.687,1.016 2.597,1.129 2.565,1.27
  Multi-Layer board cut-out: -3.225,1.27 -3.193,1.411 -3.103,1.524 -2.972,1.587 -2.828,1.587 -2.697,1.524 -2.607,1.411 -2.575,1.27 -2.575,1.27 -2.607,1.129 -2.697,1.016 -2.828,0.953 -2.972,0.953 -3.103,1.016 -3.193,1.129 -3.225,1.27
  silkscreen extent -4.5,-5.03 4.5,0.69
WIFI-SMD_ESP32-S2-WROVER-I [mm]
  rect 1.8x1 smd: 1(-9,11.75) 2(-9,10.25) 3(-9,8.75) 4(-9,7.25) 5(-9,5.75) 6(-9,4.25) 7(-9,2.75) 8(-9,1.25) 9(-9,-0.25) 10(-9,-1.75) 11(-9,-3.25) 12(-9,-4.75) 13(-9,-6.25) 14(-9,-7.75) 15(-9,-9.25) 16(-9,-10.75) 27(9,-10.75) 28(9,-9.25) 29(9,-7.75) 30(9,-6.25) 31(9,-4.75) 32(9,-3.25) 33(9,-1.75) 34(9,-0.25) 35(9,1.25) 36(9,2.75) 37(9,4.25) 38(9,5.75) 39(9,7.25) 40(9,8.75) 41(9,10.25) 42(9,11.75)
  rect 1x1.8 smd: 17(-6.75,-11.75) 18(-5.25,-11.75) 19(-3.75,-11.75) 20(-2.25,-11.75) 21(-0.75,-11.75) 22(0.75,-11.75) 23(2.25,-11.75) 24(3.75,-11.75) 25(5.25,-11.75) 26(6.75,-11.75)
  rect 1.1x1.1 smd: 43(-2.69,5.2) 43(-2.69,2.2) 43(-2.69,3.7) 43(-1.19,5.2) 43(-1.19,3.7) 43(-1.19,2.2) 43(0.31,5.2) 43(0.31,3.7) 43(0.31,2.2)
  silkscreen extent -10.19,-11.81 9.02,19.25
WSON-6_L2.0-W2.0-P0.65-TL-EP [mm]
  oval 0.607x0.364 smd: 1(-1.028,0.65) 2(-1.028,0) 3(-1.028,-0.65) 4(1.028,-0.65) 5(1.028,0) 6(1.028,0.65)
  rect 1x1.6 smd: 7(0,0)
  silkscreen extent -1.71,-1.08 1.08,1.08
X1SON-2_L1.0-W0.6-P0.65-RD [mm]
  rect 0.4x0.6 smd: 1(-0.325,0) 2(0.325,0)
  silkscreen extent -0.83,-0.43 0.66,0.43
X1SON-2_L1.0-W0.6-P0.65-RD-1 [mm]
  rect 0.4x0.6 smd: 1(-0.325,0) 2(0.325,0)
  silkscreen extent -0.83,-0.43 0.66,0.43

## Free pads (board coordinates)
  round 60 hole 118.11: 2(3461.18,3555.67) 2(3461.18,6547.81) 2(6847.01,3555.67) 2(6847.01,6547.8)

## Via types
v1: diameter 24, hole 12, Top Layer to Bottom Layer, 51 vias
v2: diameter 24.02, hole 12.01, Top Layer to Bottom Layer, 23 vias
v3: diameter 27.56, hole 13.78, Top Layer to Bottom Layer, 21 vias
v4: diameter 24.41, hole 12.2, Top Layer to Bottom Layer, 4 vias

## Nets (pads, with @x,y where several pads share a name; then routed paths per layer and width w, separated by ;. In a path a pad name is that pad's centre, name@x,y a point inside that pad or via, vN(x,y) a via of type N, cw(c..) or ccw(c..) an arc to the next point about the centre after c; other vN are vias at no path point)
1D+: R17.2 U2U.A6 U2U.B6 U12.1 | length 446.2
  Top Layer w10.63: v1(5700.47,6615) 5705,6615 5732.16,6587.84 5732.16,6557.2 U2U.B6 ; v1(5786.7,6615.01) 5771.53,6599.84 5771.53,6557.2 U2U.A6 5770,6555.35 5770,6446.54 5790,6426.54 R17.2
  Bottom Layer w10.63: v1(5700.47,6615) 5701.5,6616.03 v1@5706.03,6616.03 ; U12.1 5731.69,6675.52 5731.69,6641.69 v1@5706.03,6616.03 ; v1(5786.7,6615.01) 5707.04,6615.01 v1@5706.03,6616.03
1D-: R1.2 U2U.A7 U2U.B7 U11.1 | length 449.8
  Top Layer w10.63: R1.2 5730,6426.54 5750.16,6446.7 U2U.A7 5750.16,6620.16 5770,6640 v2(5835,6640) 5810,6615 5810,6602.59 5789.09,6581.68 5789.09,6555.95 U2U.B7
  Bottom Layer w10.63: U11.1 5822.21,6640 v2(5835,6640)
3.3: C1.2 C3.2 C5.2 C7.1 C9.2 C10.2 CP2102N.6 CP2102N.7 HX711.10 MAX6675_1.5 MAX6675_2.5 MAX6675_3.5 MPU.13 R2.2 R13.2 R14.2 R15.2 R16.2 R24.1 R25.2 R30.1 R31.1 REG_3.3V.1 REG_3.3V.2 RF.1 SD1.4 U24.2 | length 669.1
  Top Layer w10: MAX6675_1.5 4439.66,3860 R14.2 ; CP2102N.7 CP2102N.6
  Top Layer w10.63: v2(5974.13,3932.72) 5976.41,3935 R25.2 ; v2(5974.13,4002.28) 5976.84,4005 R24.1 ; MPU.13 6350,4049.56 v3(6350,4085) ; C9.2 v3(6608.58,3909.99)
$1N8: R21.2 USB.B5 | length 140.6
  Top Layer w10: R21.2 4514.66,6479.66 4551.1,6516.1 USB.B5
$1N9: R20.2 USB.A5 | length 150.8
  Top Layer w10: USB.A5 4669.21,6525.79 4730.34,6464.66 R20.2
$1N18: CP2102N.8 R3.1 R4.2 | length 156.5
  Top Layer w10: R4.2 R3.1 4970.97,5592.54 CP2102N.8
$1N23: CP2102N.9 R2.1 | length 110.2
  Top Layer w10: R2.1 4986.64,5549.03 CP2102N.9
$1N36: PYRO_3.2 Q2.3 | length 255.7
  Bottom Layer w10: Q2.3 6754.2,6170 PYRO_3.2
$1N40: Q4.1 R9.2 R10.2 | length 197.2
  Bottom Layer w10: R9.2 R10.2 6568.2,5480 Q4.1
$1N41: PYRO_1.2 Q4.3 | length 267.4
  Bottom Layer w10: Q4.3 6880,5520 PYRO_1.2
$1N48: PYRO_2.2 Q5.3 | length 272.4
  Bottom Layer w10: Q5.3 6890,5870 PYRO_2.2
$1N49: Q5.1 R11.2 R12.2 | length 190.8
  Bottom Layer w10: R11.2 R11.2@6507.06,5832.6 ; R12.2 6509.66,5830 R11.2@6507.06,5832.6 ; Q5.1 R11.2@6507.06,5832.6
$1N68: R5.2 U2U.A5 | length 153.8
  Top Layer w10.63: U2U.A5 5809.21,6481.13 R5.2
$1N69: R6.2 U2U.B5 | length 149.7
  Top Layer w10.63: R6.2 5691.1,6471.44 U2U.B5
$1N96: Q2.1 R7.2 R8.2 | length 162.1
  Bottom Layer w10: R7.2 R8.2 6532.06,6192.6 Q2.1
$1N98: PWR_LED.2 R15.1 | length 204.3
  Top Layer w10: R15.1 4795,5805.34 4795,5890 4805.04,5900.04 PWR_LED.2
$1N99: R16.1 USER_LED.2 | length 131.4
  Top Layer w10: USER_LED.2 4974.96,4989.96 4990.34,5005.34 R16.1
$1N102: HX711.1 LOAD_CELL.1 | length 732.2
  Top Layer w10: HX711.1@6440,4590 6640,4590 6765,4465 6765,4350 LOAD_CELL.1
$1N103: HX711.2 LOAD_CELL.2 | length 682.2
  Top Layer w10: HX711.2@6440,4690 6640,4690 6935,4395 LOAD_CELL.2
$1N104: HX711.5 LOAD_CELL.5 | length 582
  Top Layer w10: HX711.5@6440,4990 6640,4990 6725,4990 LOAD_CELL.5
$1N105: HX711.4 LOAD_CELL.4 | length 602.7
  Top Layer w10: HX711.4@6440,4890 6640,4890 6675,4890 LOAD_CELL.4
$1N106: HX711.3 LOAD_CELL.3 | length 632.2
  Top Layer w10: HX711.3@6440,4790 6640,4790 6640,4775 LOAD_CELL.3
$1N118: C6.2 MPU.20 | length 169.2
  Top Layer w10: C6.2 6170,4025 6195.43,3999.57 MPU.20
$1N121: C9.1 MPU.8 | length 131.3
  Top Layer w10: MPU.8 6466.93,3940.51 C9.1
$1N123: R26.1 SD1.2 | length 239.5
  Bottom Layer w10: R26.1 3690,3965.04 3754.53,3900.51 3774.99,3900.51 3840.04,3835.46 SD1.2
$1N125: R27.1 SD1.3 | length 208.1
  Bottom Layer w10: R27.1 3883.35,3876.99 SD1.3
$1N129: C10.1 C11.2 | length 74.9
  Bottom Layer w10: C10.1 C11.2
$1N131: R28.1 SD1.5 | length 250.7
  Bottom Layer w10: SD1.5 3969.96,3830 3970.55,3830.59 3970.55,3870.55 4080.34,3980.34 R28.1
$1N134: R29.1 SD1.7 | length 249.2
  Bottom Layer w10.63: SD1.7 4071.85,3830.28 4071.85,3851.18 4085.67,3865 4106.57,3865 4221.91,3980.34 R29.1
$1N147: Q1.1 R32.1 | length 80.3
  Top Layer w10: R32.1 5500.72,5249.28 Q1.1
$1N149: Q3.1 R33.1 | length 87.4
  Top Layer w10: R33.1 5298.86,5164.03 Q3.1
$1N190: HX711.6 LOAD_CELL.6 | length 561.3
  Top Layer w10: HX711.6@6440,5090 6640,5090 6775,5090 LOAD_CELL.6
$1N2149: C8.2 MPU.10 | length 133.2
  Top Layer w10: MPU.10 6462.32,3979.88 C8.2
+5V: C4.2 C12.2 D1.1 D2.1 R4.1 REG_3.3V.4 REG_3.3V.6 REG_5V.1 REG_5V.2 SERVO.2 U2U.A4B9 U2U.B4A9 USB.A4B9 USB.B4A9 | length 970.2
  Top Layer w10: R4.1 4974.03,5689.03 v1(5020,5735) ; REG_5V.1 REG_5V.2
  Bottom Layer w10: v1(5020,5735) 5020,5925 v2(5135,6040)
  Bottom Layer w10.63: v1(5665,6641.93) D1.1
  Bottom Layer w19.68: v2(5900,6240) 6050,6090 6050,5995 6095,5950 SERVO.2
  Bottom Layer w20: v4(4472.2,6657.96) 4500.75,6657.96 D2.1
CD: R31.2 SD1.9 SD1.10 U24.27 | length 2118.4
  Top Layer w10: v1(3720,3885) 3740,3905 v1(3895,3905) 4520,3905 v1(4615,3810) ; U24.27 4976.77,4208.23 5120,4065 5120,3840 v1(5090,3810)
  Bottom Layer w10: v1(3720,3885) 3710.12,3875.12 SD1.9 SD1.10 ; R31.2 3895,3935.34 v1(3895,3905) ; v1(4615,3810) v1(5090,3810)
CLK: HX711.9 TL_1.4 U24.14 | length 1538.4
  Top Layer w10: U24.14 5715.12,4090.12 5750,4125 5750,4325 5550,4525 5550,4810 HX711.9 6050,4900 TL_1.4
CS: R26.2 R30.2 TL_3.1 U24.25 | length 2902.3
  Top Layer w10: U24.25 5083.3,4191.7 v1(5145,4130)
  Bottom Layer w10: TL_3.1 3430,3950 ; R30.2 3865.34,4030.34 3845,4010 3719.66,4010 R26.2 3634.66,4039.66 3545,3950 3430,3950 ; v1(5145,4130) 5145,3785 5105.28,3745.28 3634.72,3745.28 3430,3950
CS1: MAX6675_1.2 TL_2.1 U24.36 | length 1823.5
  Top Layer w19.68: TL_2.1 4280,4275 MAX6675_1.2 4878.27,3676.73 U24.36
CS2: MAX6675_2.2 TL_2.3 U24.34 | length 2433.5
  Top Layer w19.68: TL_2.3 3520,4735 4290,4735 MAX6675_2.2 4535,4690 4535,4145 4885,3795 4935.51,3795 U24.34
CS3: MAX6675_3.2 TL_2.5 U24.32 | length 3152.9
  Top Layer w19.68: TL_2.5 4005,5520 MAX6675_3.2 4615,5285 4615,4185 4887.05,3912.95 U24.32
D+: R22.2 U28.1 USB.A6 USB.B6 | length 365.1
  Top Layer w7.99: v4(4580,6625) 4590.47,6614.53 USB.B6 ; v4(4640,6620) 4629.84,6609.84 USB.A6 4629.84,6525.16 4650,6505 R22.2
  Bottom Layer w7.99: U28.1 4590,6635 v4(4580,6625) 4585,6620 v4(4640,6620)
D-: R23.2 U15.1 USB.A7 USB.B7 | length 360.3
  Top Layer w7.99: R23.2 4585,6500 4610,6525 USB.A7 4610.16,6625.16 4635,6650 v4(4650,6650) 4665,6635 4665,6610 4649.53,6594.53 USB.B7
  Bottom Layer w7.99: v4(4650,6650) U15.1
D/O: HX711.8 TL_1.3 U24.13 | length 1430.5
  Top Layer w10: U24.13 5721.06,4031.06 5780,4090 5780,4660 HX711.8 6100,4800 TL_1.3
DIN_LED: LEDs.1 U24.15 | length 1360.2
  Top Layer w10: U24.15 v1(5710,4149.17) ; v1(5802.98,4149.17) v1(6105,4149.17)
  Bottom Layer w10: v1(5710,4149.17) v1(5802.98,4149.17) ; v1(6105,4149.17) 6620.83,4149.17 6825,3945 LEDs.1
DTR: CP2102N.28 Q3.3 R32.2 | length 588
  Top Layer w10: CP2102N.28 5203.51,5360 v1(5210,5360) ; Q3.3 5405,5039.32 v1(5405,5175) ; v1(5390,5360) R32.2 5404.03,5250.97 v1(5405,5250)
  Bottom Layer w10: v1(5210,5360) v1(5390,5360) ; v1(5405,5175) v1(5405,5250)
EN: BOOT.1 BOOT.2 Q1.3 R14.1 U24.41 | length 2977.3
  Top Layer w10: BOOT.1 4266.07,3650 4515,3650 4550.35,3614.65 BOOT.2 4636.76,3603.58 R14.1 4858.88,3381.46 U24.41 5091.46,3381.46 v1(5100,3390) ; v1(5305,4355) 5532.84,4582.84 Q1.3
  Bottom Layer w10: v1(5100,3390) 5100,3630 5305,3835 v1(5305,4355)
GND: BOOT.3 BOOT.4 C1.1 C2.1 C3.1 C4.1 C5.1 C6.1 C7.2 C8.1 C11.1 C12.1 CP2102N.3 CP2102N.29 D1.2 D2.2 HX711.7 LEDs.2 MAX6675_1.4 MAX6675_2.4 MAX6675_3.4 MPU.18 power.1 PWR_LED.1 PYRO_PWR.2 Q2.2 Q4.2 Q5.2 R3.2 R5.1 R6.1 R8.1 R10.1 R11.1 R20.1 R21.1 REG_3.3V.3 REG_3.3V.5 REG_3.3V.7 REG_5V.3 REG_5V.5 REG_5V.7 RF.2 RST.3 RST.4 SD1.6 SD1.11 SD1.12 SERVO.3 TL_U2U.2 U2U.1 U2U.2 U2U.3 U2U.4 U2U.A1B12 U2U.B1A12 U11.2 U12.2 U15.2 U24.1 U24.26 U24.42 U24.43 U28.2 USB.1 USB.2 USB.3 USB.4 USB.A1B12 USB.B1A12 | length 4676.7
  Top Layer w10: USB.2 4469.61,6584.92 USB.B1A12 ; BOOT.4 4753.58,3426.42 4857.6,3322.4 U24.42 5112.4,3322.4 5277.79,3487.79 v3(5277.79,3551.58) U24.43@5277.79,3580.27 ; USB.A1B12 4765.67,6560.51 USB.1 ; C5.1 v1(4835,5420) ; C3.1 v1(4890,5475) ; v1(4905,5660) R3.2 ; v1(4910,5770) PWR_LED.1 ; CP2102N.29 5087.83,5420 CP2102N.3 5142.27,5472.27 5170,5500 v1(5195,5500) ; v1(5177.44,6095) 5177.44,6077.91 5220,6035.35 REG_3.3V.5 REG_3.3V.7 5220,5979.96 5245.59,5954.37 REG_3.3V.3 5245.59,5891.97 C1.1 ; REG_5V.5 REG_5V.7 5230,6305.72 5255.59,6280.13 v1(5255.59,6254.51) ; U24.43@5277.79,3698.38 5336.85,3698.38 v3(5367.11,3698.38) 5395.9,3698.38 5395.9,3639.33 v3(5367.75,3639.33) 5336.85,3639.33 v3(5306.88,3639.33) 5277.79,3639.33 U24.43@5277.79,3580.27 ; U24.1 5563.5,3322.4 5395.9,3490 v3(5395.9,3548.7) 5395.9,3580.27 v3(5366.47,3580.27) 5336.85,3580.27 v3(5307.84,3580.27) U24.43@5277.79,3580.27 ; C6.1 6217.44,4187.56 ; MPU.18 6250.8,4154.2 6217.44,4187.56 ; C8.1 6380,4187.56 C7.2 6217.44,4187.56
  Top Layer w20: U2U.2 5614.33,6555.51 U2U.B1A12 ; U2U.A1B12 5905.67,6555.51 U2U.1
  Top Layer w25: power.1 5207.44,6592.56 C2.1
  Bottom Layer w10: R10.1 6490.34,5530 6543.4,5530 Q4.2 ; R11.1 6445.34,5880.34 6472.4,5907.4 Q5.2 ; R8.1 6470.34,6235.34 6502.4,6267.4 Q2.2
  Bottom Layer w10.63: SD1.6 4013.27,3845.24 v3(4048.27,3880.24) ; C11.1 v3(4015,4245.39) ; D2.2 v1(4525,6749.57) ; U28.2 v1(4590,6743.07) ; U15.2 v1(4650,6743.07) ; D1.2 v1(5665,6743.07) ; U12.2 v1(5730,6743.07) ; U11.2 v1(5800,6743.07) ; v2(6370,5482.01) 6372.01,5480 R10.1 ; v2(6400.98,5780) 6445.34,5824.36 R11.1 ; v2(6415.47,6195) R8.1
  other v1: 5282.56,6190 5565.34,6445 4440.34,6460 4809.66,6460
  other v2: 6145,3405 6528.49,3405 5305,3700 6579.72,3999.24 5024.26,4281.85 5198.5,6315 5943.03,6441.73
  other v3: 4550,3400 4175,3425 4160,3495 3655,3500 5336.85,3611.17 5258.1,3639.33 5425,3640 5336.85,3668.19 5395.9,3723.13 5280,3725
IO0: Q3.2 R13.1 RST.1 RST.2 U24.3 | length 2838.9
  Top Layer w10: Q3.2 5380,4977.11 v1(5380,4940) ; U24.3 5900.17,3440.51 R13.1 ; v1(6065,3695) 6065,3605.34 R13.1 ; RST.2 6443.93,3665 6226.07,3665 RST.1 6166.07,3605 R13.1
  Bottom Layer w10: v1(5380,4940) 5380,4505 5440,4445 5440,4140 5885,3695 v1(6065,3695)
LED_USER: U24.24 USER_LED.1 | length 726.9
  Top Layer w10: USER_LED.1 5035.04,4734.96 5142.36,4627.64 U24.24
MISO: MAX6675_1.1 MAX6675_2.1 MAX6675_3.1 R29.2 TL_2.4 U24.31 | length 3753.3
  Top Layer w19.68: TL_2.4 3435,4800 4080,4800 4215,4935 MAX6675_2.1 ; U24.31 4937.68,3970 v1(5005,3970)
  Bottom Layer w19.68: R29.2 4225,4090 MAX6675_1.1 ; MAX6675_3.1 4480,5520 4480,4980 ; MAX6675_2.1 4435,4935 4480,4980 ; v1(5005,3970) 4685,3970 MAX6675_1.1 ; MAX6675_1.1 4480,4345 4480,4980
MOSI: R27.2 TL_3.2 U24.29 | length 2085.3
  Top Layer w10: U24.29 4999.88,4090.12 v1(5010,4080)
  Bottom Layer w10: TL_3.2 3719.66,4100 R27.2 3780,4060 3812.99,4092.99 3885.77,4092.99 3895,4083.76 3895,4046.24 3925.41,4015.83 4082.55,4015.83 4085.57,4012.8 4412.2,4012.8 4508.86,3916.14 5017.16,3916.14 5051.69,3950.66 5051.69,4019.98 5047.98,4023.69 5047.98,4042.02 v1(5010,4080)
PYRO-1: R9.1 U24.17 | length 1782.4
  Top Layer w10: U24.17 5567.6,4247.6 v1(5635,4315) ; v1(5810,4325) v1(6140,4325)
  Bottom Layer w10: v1(5635,4315) 5645,4325 v1(5810,4325) ; v1(6140,4325) 6160,4325 6235,4400 6235,5149.66 R9.1
PYRO-2: R12.1 U24.18 | length 1915.3
  Top Layer w10: U24.18 5496.69,4331.69 v1(5505,4340)
  Bottom Layer w10: v1(5505,4340) 5885,4720 5885,5240 6360,5715 R12.1
PYRO-3: R7.1 U24.19 | length 2280.2
  Top Layer w10: U24.19 5437.63,4327.63 v1(5465,4355)
  Bottom Layer w10: v1(5465,4355) 5465,4910 6370,5815 6370,5885 6470.34,5985.34 R7.1
PYRO_5V: PYRO_PWR.1 PYRO_SWT.1 | length 936.9
  Top Layer w20: PYRO_SWT.1@6300,5840 6300,5700 6420,5580 6630,5580 PYRO_PWR.1
PYRO_ARM: PYRO_1.1 PYRO_2.1 PYRO_3.1 PYRO_SWT.2 | length 1606.2
  Top Layer w20: PYRO_SWT.2@6300,5940 6340,5980 PYRO_2.1 6940,5970 7035,5970 7065,6000 ; PYRO_1.1 7065,5775 7065,6000 ; PYRO_3.1 7065,6180 7065,6000
RF_RX: RF.4 TL_RF.2 U24.37 | length 5244.8
  Top Layer w10: TL_RF.2 4082.99,6572.99 4082.99,6242.99 4177.99,6147.99 4187.99,6147.99 RF.4 ; v1(4750,3568.32) 4776.68,3595 4867.56,3595 4890.24,3617.68 U24.37
  Bottom Layer w10: RF.4 4187.99,6147.99 4171.37,6147.99 3255,5231.62 3255,3773.38 3368.38,3660 3575,3660 3659.68,3575.32 4743,3575.32 v1(4750,3568.32)
RF_TX: RF.3 TL_RF.1 U24.38 | length 5250
  Top Layer w10: TL_RF.1 4067.01,6572.99 4067.01,6236.37 4171.37,6132.01 4187.99,6132.01 RF.3 ; v2(4785,3570) 4794.02,3579.02 4869.84,3579.02 4890.24,3558.62 U24.38
  Bottom Layer w10: RF.3 4187.99,6132.01 4177.99,6132.01 3270.98,5225 3270.98,3780 3375,3675.98 3581.62,3675.98 3666.3,3591.3 3772.61,3591.3 3786.31,3605 3832.61,3605 3846.31,3591.3 3892.61,3591.3 3906.31,3605 3952.61,3605 3966.31,3591.3 4012.61,3591.3 4026.31,3605 4072.61,3605 4086.31,3591.3 4763.7,3591.3 v2(4785,3570)
RTS: CP2102N.24 Q1.2 R33.2 | length 409.5
  Top Layer w10: CP2102N.24 5246.18,5205.97 R33.2 5268.05,5220 5427.11,5220 Q1.2
SCK: MAX6675_1.3 MAX6675_2.3 MAX6675_3.3 R28.2 TL_2.2 U24.30 | length 4322.4
  Top Layer w19.68: MAX6675_2.3 4325,4670 3605,4670 TL_2.2 3255,4320 3255,4215 3280,4190 3455,4190 3550,4095 v2(4118.89,4095) 4360,4095 MAX6675_1.3 ; U24.30 5013.94,4031.06 v1(5025,4020)
  Bottom Layer w19.68: v2(4118.89,4095) 4120,4093.89 R28.2 ; MAX6675_3.3 4345,5420 4280,5355 4280,4845 MAX6675_2.3 ; MAX6675_1.3 4545,4060 4670,3935 5009.35,3935 5032.83,3958.47 5032.83,4012.17 v1(5025,4020)
SCL: MPU.23 R24.2 TL_1.2 U24.12 | length 1381.6
  Top Layer w10: U24.12 5837.01,3972.01 5925,4060 v2(5942.68,4060) 6085,4060 6104.66,4040.34 R24.2 6137.31,4005 6202.31,3940 6220.76,3940 MPU.23
  Bottom Layer w10: v2(5942.68,4060) 5942.68,4492.68 TL_1.2
SDA: MPU.24 R25.1 TL_1.1 U24.11 | length 1320.4
  Top Layer w10: U24.11 5942.05,3912.95 5972.5,3882.5 v2(5997.12,3882.5) 6052.16,3882.5 R25.1 6175,3935 6190,3920 6220.44,3920 MPU.24
  Bottom Layer w10: v2(5997.12,3882.5) 5997.12,4397.12 TL_1.1
SERVO_HIGH: SERVO.1 TL_1.5 U24.16 | length 1954.2
  Top Layer w19.68: U24.16 5644.63,4207.93 v1(5715,4207.93)
  Top Layer w20: TL_1.5 6145,5145 SERVO.1
  Bottom Layer w19.68: v1(5715,4207.93) 5822.93,4207.93 5845,4230 5845,4555 5925,4635 5925,4925 TL_1.5
U2U_RX: CP2102N.25 TL_U2U.1 U24.21 | length 3412.9
  Top Layer w10: CP2102N.25 5144.92,5335.08 5147.54,5335.08 5185.99,5296.62 5209.23,5296.62 6315,6402.39 6315,6535 6420,6640 TL_U2U.1 ; U24.21 5319.52,4240.98 5338,4222.5 v1(5338,4195)
  Bottom Layer w10: v2(5235,5310) 5223.8,5310 5214.23,5300.43 5214.23,4640.77 5425.98,4429.02 5425.98,4168.38 5406.62,4149.02 5364.36,4149.02 5345,4168.38 5345,4188 v1(5338,4195)
U2U_TX: CP2102N.26 TL_U2U.3 U24.20 | length 3417
  Top Layer w10: CP2102N.26 5158.83,5349 5158.83,5346.38 5192.61,5312.61 5202.61,5312.61 6138.42,6248.42 6138.42,6262.56 6173.78,6297.92 6187.92,6297.92 6223.28,6333.28 6223.28,6347.42 6258.63,6382.77 6272.77,6382.77 6299.02,6409.02 6299.02,6535 6194.02,6640 TL_U2U.3 ; v1(5367.98,4195) 5367.98,4230.38 5378.58,4240.98 U24.20
  Bottom Layer w10: v2(5210,5330) 5210,5318.8 5198.25,5307.05 5198.25,5142.78 5191.18,5135.71 5187.07,5135.71 5180,5128.64 5180,5082.78 5187.07,5075.71 5191.18,5075.71 5198.25,5068.64 5198.25,5022.78 5191.18,5015.71 5187.07,5015.71 5180,5008.64 5180,4962.78 5187.07,4955.71 5191.18,4955.71 5198.25,4948.64 5198.25,4902.78 5191.18,4895.71 5187.07,4895.71 5180,4888.64 5180,4842.78 5187.07,4835.71 5191.18,4835.71 5198.25,4828.64 5198.25,4634.15 5410,4422.39 5410,4175 5400,4165 5370.98,4165 5360.98,4175 5360.98,4188 v1(5367.98,4195)
UART_D+: CP2102N.4 R17.1 | length 1149.1
  Top Layer w10.63: CP2102N.4 5126.19,5488.36 5768.31,6130.48 5768.31,6338.65 R17.1
UART_D-: CP2102N.5 R1.1 | length 1152.1
  Top Layer w10.63: CP2102N.5 5114.43,5500.11 5593.54,5979.22 5593.54,5993.54 5628.81,6028.81 5643.12,6028.81 5678.39,6064.07 5678.39,6078.39 5713.66,6113.66 5727.98,6113.66 5751.69,6137.37 5751.69,6338.65 R1.1
USB_D+: R22.1 U24.22 | length 2440.4
  Top Layer w10: v2(4632.5,6314.8) 4625.49,6321.81 4625.49,6349.96 4650,6374.46 R22.1 ; v1(5226.67,4454.92) 5226.67,4440.02 5238.42,4428.27 5238.42,4315.08 5260.47,4293.03 U24.22
  Bottom Layer w10: v2(4632.5,6314.8) 4625.49,6307.8 4625.49,5041.2 5211.77,4454.92 v1(5226.67,4454.92)
USB_D-: R23.1 U24.23 | length 2440
  Top Layer w10: R23.1 4585,6374.46 4609.51,6349.96 4609.51,6321.81 v2(4602.5,6314.8) ; v1(5200.47,4428.72) 5215.37,4428.72 5222.44,4421.65 5222.44,4314.06 5201.41,4293.03 U24.23
  Bottom Layer w10: v2(4602.5,6314.8) 4609.51,6307.8 4609.51,5034.58 5200.47,4443.62 v1(5200.47,4428.72)
VIN: C2.2 power.2 REG_5V.4 REG_5V.6 | length 384
  Top Layer w20: REG_5V.6 5204.41,6367.42 5220.41,6383.42 5262.07,6383.42 5262.56,6383.92 ; REG_5V.4 5262.56,6362.46 5262.56,6383.92 ; C2.2 5262.56,6383.92
  Top Layer w25: C2.2 5262.56,6592.56 power.2
pads on no net: CP2102N.1 CP2102N.2 CP2102N.10 CP2102N.11 CP2102N.12 CP2102N.13 CP2102N.14 CP2102N.15 CP2102N.16 CP2102N.17 CP2102N.18 CP2102N.19 CP2102N.20 CP2102N.21 CP2102N.22 CP2102N.23 CP2102N.27 MPU.1 MPU.2 MPU.3 MPU.4 MPU.5 MPU.6 MPU.7 MPU.9 MPU.11 MPU.12 MPU.14 MPU.15 MPU.16 MPU.17 MPU.19 MPU.21 MPU.22 PYRO_SWT.3 RF.5 SD1.1 SD1.8 U2U.A8 U2U.B8 U24.4 U24.5 U24.6 U24.7 U24.8 U24.9 U24.10 U24.28 U24.33 U24.35 U24.39 U24.40 USB.A8 USB.B8

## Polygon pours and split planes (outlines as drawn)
3.3 on Bottom Layer (solid, remove dead copper, pour order 4): 3070,6910 7310,6910 7310,3100 3070,3100
3.3 on Top Layer (solid, remove dead copper, pour order 2): 3000,7005 7395,7005 7395,3000 3000,3000
+5V on Top Layer (solid, remove dead copper, pour order 0): 4380,6875 4380,6255 4620,6015 5720,6015 6010,6305 6010,6885 4390,6885

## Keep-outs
Board Outline Layer:
  lines w10: 3185.59,3555.67 ccw(c3461.18,3555.67) 3461.18,3280.08 6847,3280.08 ccw(c6847,3555.67) 7122.59,3555.67 7122.59,6547.79 ccw(c6847,6547.79) 6847,6823.38 3461.18,6823.38 ccw(c3461.18,6547.79) 3185.59,6547.79 3185.59,3555.67

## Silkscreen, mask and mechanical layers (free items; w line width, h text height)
Top Silkscreen Layer:
  text "C2" at 5483.69,6702.81 h45
  text "C2" at 5486.05,6697.3 h45
  text "??" at 5000,4440 h393.7
Bottom Silkscreen Layer:
  text "GND" at 6325,6705 h31.5
  text "TX" at 4020,6700 h31.5
  text "RX" at 4170,6700 h31.5
  text "GND" at 5185,6700 h31.5
  text "VIN" at 5340,6700 h31.5
  text "TX" at 6170,6700 h31.5
  text "RX" at 6470,6700 h31.5
  text "KVR" at 3820,6660 h118.11
  text "SERVO" at 6325,5180 h31.5 r90
  text "CLK" at 6320,5010 h31.5 r90
  text "B+" at 6875.45,4957.91 h31.5 r90
  text "CS3" at 3560.45,4902.91 h31.5 r90
  text "D/0" at 6325,4855 h31.5 r90
  text "B-" at 6880,4800 h31.5 r90
  text "MISO" at 3565.45,4747.91 h31.5 r90
  text "SCL" at 6320,4700 h31.5 r90
  text "A+" at 6875.45,4652.91 h31.5 r90
  text "CS2" at 3560,4615 h31.5 r90
  text "SDA" at 6325,4550 h31.5 r90
  text "A-" at 6880.45,4512.91 h31.5 r90
  text "SCK" at 3555.45,4457.91 h31.5 r90
  text "E-" at 6885.45,4362.91 h31.5 r90
  text "Rated for High-Temp Ops" at 4710,4330 h118.11 r270
  text "CS1" at 3552.31,4302.91 h31.5 r90
  text "E+" at 6885.45,4217.91 h31.5 r90
  text "MOSI" at 3555,4130 h31.5 r90
  text "AGNI" at 4705,4060 h905.51 r270
  text "CS" at 3560.45,3977.91 h31.5 r90
  text "DIN" at 7020.45,3972.91 h31.5 r90
  text "GND" at 7015.45,3817.91 h31.5 r90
